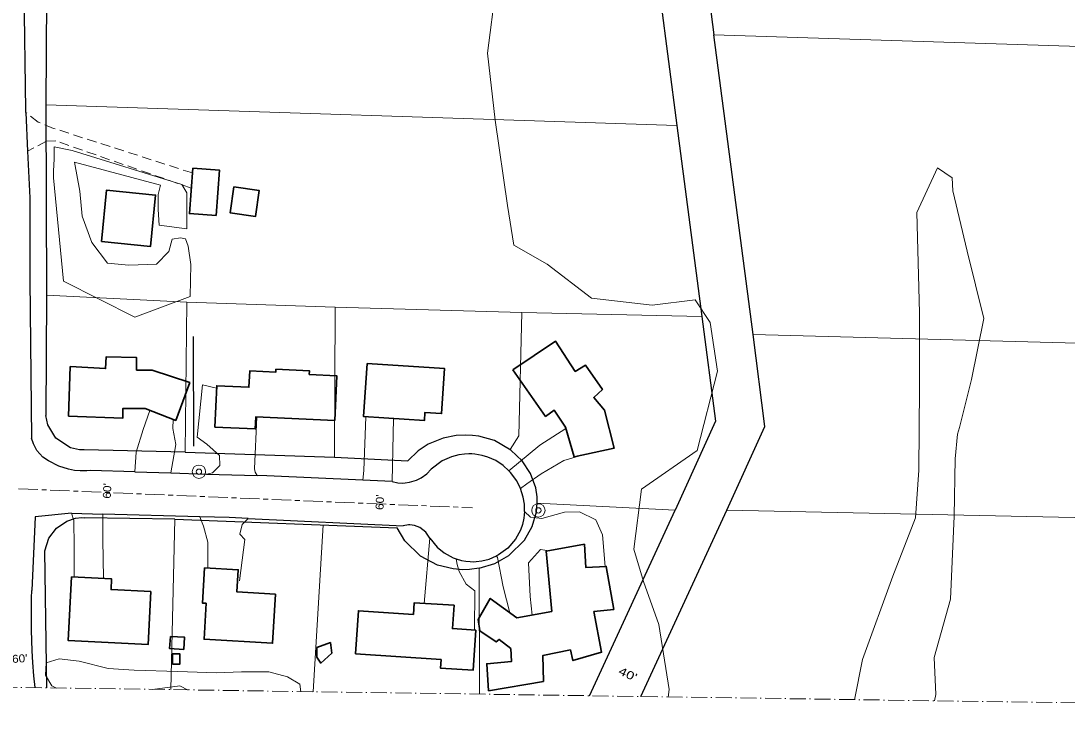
# Model space of a CAD drawing. Extents: x -861682 to -858969, y -1797841 to -1795153.
# Drawn here: x -860350 to -859566, y -1797836 to -1797317 of the extents above; entities that cross this region are included whole.
import ezdxf

# ---------------------------------------------------------------- set-up
doc = ezdxf.new("R2010")
doc.units = 0
doc.header["$LTSCALE"] = 2.4
for name, pattern in [('DOT_DASHED', [7.7, 5, -1.2, 0.3, -1.2]), ('LONG_DASH_SHORT_DASH', [9.9, 6, -1.2, 1.5, -1.2]), ('MEDIUM_DASHED', [4.5, 3, -1.5])]:
    doc.linetypes.add(name, pattern=pattern)
for name, color, linetype, lineweight in [('10', 7, 'Continuous', 25), ('11', 7, 'Continuous', 13), ('12', 7, 'Continuous', 35), ('14', 7, 'Continuous', 25), ('18', 7, 'Continuous', 13), ('30', 7, 'Continuous', 13), ('31', 7, 'Continuous', 13), ('32', 7, 'LONG_DASH_SHORT_DASH', 13), ('42', 7, 'Continuous', 25), ('61', 7, 'Continuous', 13)]:
    doc.layers.add(name, color=color, linetype=linetype, lineweight=lineweight)
doc.layers.add('43', color=7, linetype='Continuous')

msp = doc.modelspace()

# ---------------------------------------------------------------- linework, layer by layer
at = {"layer": '10'}
for p, q in [((-860346.092, -1797386.021), (-860344.837, -1797414.894)), ((-860264.541, -1797655.175), (-860297.626, -1797654.184)), ((-860264.541, -1797655.175), (-860237.512, -1797655.986)), ((-860237.512, -1797655.986), (-860210.664, -1797656.791)), ((-860210.664, -1797656.791), (-860172.696, -1797657.929)), ((-860071.585, -1797662.487), (-860093.426, -1797661.477)), ((-860311.905, -1797686.124), (-860288.485, -1797686.779)), ((-860215.707, -1797688.816), (-860288.485, -1797686.779)), ((-860179.59, -1797690.091), (-860063.186, -1797695.517))]:
    msp.add_line(p, q, dxfattribs=at)
for points in [[(-860346.092, -1797386.021), (-860346.181, -1797383.977), (-860347.486, -1797294.242), (-860348.717, -1797244.699)], [(-860344.837, -1797414.894), (-860343.319, -1797449.854), (-860343.308, -1797511.255), (-860341.886, -1797630.037)], [(-860329.301, -1797646.991), (-860333.385, -1797644.118), (-860337.927, -1797639.066), (-860340.551, -1797634.233), (-860341.886, -1797630.037)], [(-859984.071, -1797654.346), (-859988.342, -1797650.355), (-859993.871, -1797646.742), (-859999.904, -1797644.054), (-860004.131, -1797642.81), (-860009.561, -1797641.897), (-860011.759, -1797641.736), (-860013.962, -1797641.691), (-860017.264, -1797641.844), (-860021.627, -1797642.455), (-860026.949, -1797643.865), (-860033.987, -1797646.996), (-860042.218, -1797653.065), (-860045.629, -1797656.716)], [(-860297.626, -1797654.184), (-860300.412, -1797654.417), (-860302.615, -1797654.488), (-860304.263, -1797654.478), (-860305.365, -1797654.44), (-860309.753, -1797654.044), (-860314.089, -1797653.259), (-860321.447, -1797650.969), (-860329.301, -1797646.991)], [(-860093.426, -1797661.477), (-860165.596, -1797658.142), (-860172.696, -1797657.929)], [(-860071.585, -1797662.487), (-860067.268, -1797663.356), (-860063.97, -1797663.556), (-860061.768, -1797663.471), (-860058.495, -1797663.02), (-860053.231, -1797661.422), (-860049.677, -1797659.64), (-860045.629, -1797656.716)], [(-859975.225, -1797667.743), (-859978.158, -1797661.825), (-859982.714, -1797655.615), (-859984.071, -1797654.346)], [(-859972.305, -1797684.998), (-859972.265, -1797682.794), (-859972.423, -1797679.493), (-859973.269, -1797674.052), (-859975.225, -1797667.743)], [(-860311.905, -1797686.124), (-860339.289, -1797688.832), (-860341.665, -1797744.103)], [(-860179.59, -1797690.091), (-860193.81, -1797689.429), (-860215.707, -1797688.816)], [(-859972.305, -1797684.998), (-859972.778, -1797689.972), (-859973.828, -1797694.635), (-859975.298, -1797698.788), (-859978.972, -1797705.557), (-859984.713, -1797712.221), (-859991.814, -1797717.414), (-859993.235, -1797718.044)], [(-860043.312, -1797704.884), (-860046.369, -1797700.328), (-860050.716, -1797696.982), (-860054.822, -1797695.413), (-860058.237, -1797694.951), (-860059.339, -1797694.951), (-860063.186, -1797695.517)], [(-860043.312, -1797704.884), (-860037.71, -1797711.667), (-860032.579, -1797715.824), (-860025.804, -1797719.485), (-860023.446, -1797720.239)], [(-860023.446, -1797720.239), (-860019.514, -1797721.499), (-860016.264, -1797722.096), (-860012.974, -1797722.413), (-860010.771, -1797722.468), (-860008.568, -1797722.397), (-860004.193, -1797721.878), (-859998.854, -1797720.536), (-859993.235, -1797718.044)], [(-860339.286, -1797816.837), (-860340.159, -1797807.958), (-860340.924, -1797798.07), (-860341.44, -1797789.269), (-860341.765, -1797781.562), (-860341.973, -1797773.851), (-860342.038, -1797769.443), (-860342.065, -1797765.035), (-860342.065, -1797763.933), (-860342.053, -1797760.627), (-860342.002, -1797756.22), (-860341.854, -1797749.609), (-860341.665, -1797744.103)]]:
    msp.add_lwpolyline(points, dxfattribs=at)
at = {"layer": '11'}
for p, q in [((-860070.432, -1797615.281), (-860071.585, -1797662.487)), ((-860206.225, -1797655.944), (-860210.664, -1797656.791)), ((-860047.565, -1797753.678), (-860043.312, -1797704.884))]:
    msp.add_line(p, q, dxfattribs=at)
at = {"layer": '11', "linetype": 'MEDIUM_DASHED'}
for points in [[(-860221.335, -1797431.244), (-860325.343, -1797397.827), (-860336.934, -1797393.151), (-860346.092, -1797386.021)], [(-860222.156, -1797442.594), (-860323.652, -1797407.267), (-860330.736, -1797407.532), (-860344.837, -1797414.894)]]:
    msp.add_lwpolyline(points, dxfattribs=at)
at = {"layer": '11'}
for points in [[(-860203.161, -1797592.533), (-860213.809, -1797590.084), (-860217.667, -1797629.303), (-860210.561, -1797634.47), (-860201.081, -1797642.934), (-860200.815, -1797650.49), (-860206.225, -1797655.944)], [(-860253.14, -1797609.117), (-860258.31, -1797623.562), (-860263.439, -1797640.35), (-860264.541, -1797655.175)], [(-860235.636, -1797615.894), (-860235.878, -1797622.764), (-860233.705, -1797634.563), (-860237.512, -1797655.986)], [(-860173.087, -1797614.042), (-860174.827, -1797652.984), (-860174.345, -1797655.343), (-860172.696, -1797657.929)], [(-860091.193, -1797613.929), (-860092.874, -1797654.072), (-860093.426, -1797661.477)], [(-859941.369, -1797622.686), (-859960.934, -1797635.123), (-859984.071, -1797654.346)], [(-859930.166, -1797642.91), (-859942.704, -1797646.622), (-859959.904, -1797656.609), (-859970.501, -1797664.209), (-859975.225, -1797667.743)], [(-860310.055, -1797734.176), (-860309.915, -1797711.149), (-860310.23, -1797691.549), (-860311.905, -1797686.124)], [(-860287.923, -1797735.037), (-860288.446, -1797705.868), (-860288.485, -1797686.779)], [(-860209.717, -1797727.203), (-860209.795, -1797707.913), (-860212.913, -1797695.882), (-860215.707, -1797688.816)], [(-859911.916, -1797726.126), (-859913.904, -1797702.477), (-859918.909, -1797691.161), (-859930.978, -1797685.069), (-859942.312, -1797685.351), (-859959.297, -1797690.142), (-859967.802, -1797689.231), (-859972.305, -1797684.998)], [(-860185.951, -1797736.843), (-860181.936, -1797705.913), (-860185.73, -1797701.913), (-860184.106, -1797694.585), (-860179.59, -1797690.091)], [(-860009.829, -1797773.717), (-860009.618, -1797744.425), (-860016.015, -1797739.255), (-860021.249, -1797729.829), (-860022.923, -1797724.641), (-860023.446, -1797720.239)], [(-859983.274, -1797760.839), (-859988.376, -1797741.27), (-859992.479, -1797719.323), (-859993.235, -1797718.044)], [(-859953.755, -1797714.25), (-859960.385, -1797713.29), (-859969.319, -1797723.245), (-859968.037, -1797748.509), (-859966.661, -1797762.493)]]:
    msp.add_lwpolyline(points, dxfattribs=at)
at = {"layer": '12'}
for points in [[(-860221.074, -1797427.635), (-860223.536, -1797461.653), (-860203.572, -1797463.098), (-860201.109, -1797429.08)], [(-860289.577, -1797482.7), (-860252.721, -1797486.331), (-860248.926, -1797447.814), (-860285.782, -1797444.183)], [(-860190.317, -1797441.682), (-860193.073, -1797461.058), (-860173.967, -1797463.776), (-860171.21, -1797444.401)], [(-859980.997, -1797578.759), (-859956.533, -1797613.613), (-859950.175, -1797608.864), (-859941.622, -1797621.819), (-859935.156, -1797643.992), (-859905.19, -1797637.496), (-859912.389, -1797608.949), (-859920.456, -1797599.535), (-859913.868, -1797593.368), (-859926.694, -1797575.235), (-859934.232, -1797579.988), (-859948.965, -1797557.376)], [(-860313.053, -1797576.312), (-860314.085, -1797613.394), (-860273.459, -1797614.884), (-860273.487, -1797607.799), (-860256.72, -1797607.732), (-860233.777, -1797616.614), (-860223.263, -1797588.233), (-860251.404, -1797578.899), (-860263.212, -1797578.946), (-860263.25, -1797569.5), (-860285.924, -1797568.882), (-860286.36, -1797577.858)], [(-860114.514, -1797616.607), (-860173.801, -1797614.011), (-860174.193, -1797622.966), (-860204.436, -1797621.642), (-860203.082, -1797590.708), (-860178.892, -1797591.767), (-860178.357, -1797579.553), (-860158.753, -1797580.412), (-860158.659, -1797578.276), (-860133.534, -1797579.382), (-860133.659, -1797582.21), (-860113.033, -1797583.122)], [(-860090.36, -1797574.001), (-860032.248, -1797577.783), (-860034.443, -1797611.517), (-860046.932, -1797610.704), (-860047.328, -1797616.786), (-860092.952, -1797613.815)], [(-859999.399, -1797819.246), (-859958.098, -1797812.232), (-859958.648, -1797792.868), (-859937.883, -1797788.534), (-859935.962, -1797796.556), (-859914.496, -1797790.33), (-859920.286, -1797759.888), (-859905.414, -1797758.175), (-859910.975, -1797726.079), (-859926.322, -1797726.849), (-859927.337, -1797709.377), (-859956.127, -1797714.688), (-859951.932, -1797759.779), (-859978.127, -1797764.607), (-859998.023, -1797750.045), (-860007.17, -1797765.668), (-860005.718, -1797774.4), (-859993.641, -1797782.617), (-859991.287, -1797780.719), (-859982.522, -1797787.532), (-859982.011, -1797797.213), (-860000.661, -1797798.941)], [(-860212.315, -1797727.051), (-860213.862, -1797753.507), (-860211.038, -1797753.672), (-860212.61, -1797780.57), (-860161.184, -1797783.576), (-860159.037, -1797746.841), (-860187.889, -1797745.155), (-860186.918, -1797728.534)], [(-860311.948, -1797733.826), (-860314.355, -1797781.541), (-860254.535, -1797784.559), (-860252.531, -1797744.835), (-860282.31, -1797743.333), (-860281.907, -1797735.34)], [(-860098.934, -1797791.541), (-860034.917, -1797795.772), (-860035.339, -1797802.152), (-860010.883, -1797803.77), (-860008.899, -1797773.779), (-860026.307, -1797772.627), (-860025.151, -1797755.162), (-860054.964, -1797753.189), (-860055.543, -1797761.934), (-860096.793, -1797759.203)], [(-860237.851, -1797778.401), (-860227.221, -1797779.067), (-860227.796, -1797788.239), (-860238.426, -1797787.572)], [(-860128.002, -1797786.698), (-860127.972, -1797794.019), (-860125.12, -1797798.495), (-860116.649, -1797790.904), (-860117.861, -1797783.115)], [(-860236.145, -1797791.619), (-860230.713, -1797791.598), (-860230.684, -1797799.155), (-860236.115, -1797799.176)]]:
    msp.add_lwpolyline(points, close=True, dxfattribs=at)
at = {"layer": '14'}
msp.add_line((-860220.238, -1797635.926), (-860220.568, -1797553.743), dxfattribs=at)
at = {"layer": '18'}
for points in [[(-859864.604, -1797823.876), (-859863.846, -1797818.232), (-859871.598, -1797769.614), (-859883.064, -1797737.305), (-859890.246, -1797713.009), (-859884.522, -1797668.116), (-859842.837, -1797639.137), (-859827.724, -1797579.799), (-859833.066, -1797543.215), (-859844.47, -1797526.257), (-859876.572, -1797530.401), (-859922.172, -1797525.152), (-859955.337, -1797499.543), (-859980.428, -1797485.237), (-859985.033, -1797455.735), (-859994.264, -1797391.772), (-860000.133, -1797341.493), (-859993.716, -1797292.818)], [(-859664.994, -1797826.768), (-859663.802, -1797821.918), (-859665.093, -1797794.293), (-859652.988, -1797750.554), (-859650.167, -1797688.432), (-859649.394, -1797645.447), (-859647.579, -1797627.019), (-859646.185, -1797621.821), (-859637.119, -1797585.888), (-859627.855, -1797540.272), (-859640.338, -1797489.783), (-859651.146, -1797444.719), (-859651.658, -1797434.802), (-859662.787, -1797427.29), (-859678.24, -1797460.887), (-859676.049, -1797535.978), (-859676.06, -1797592.185), (-859676.758, -1797653.826), (-859679.213, -1797689.496), (-859696.277, -1797733.255), (-859718.935, -1797795.693), (-859724.851, -1797825.901)], [(-860323.199, -1797817.233), (-860326.736, -1797815.599), (-860331.491, -1797807.589), (-860331.057, -1797798.141), (-860321.149, -1797795.267), (-860306.264, -1797797.097), (-860284.515, -1797802.441), (-860264.909, -1797803.78), (-860232.314, -1797804.83), (-860203.262, -1797805.658), (-860184.608, -1797805.111), (-860164.062, -1797805.029), (-860150.113, -1797808.751), (-860140.645, -1797814.145), (-860139.938, -1797819.887)], [(-860251.296, -1797818.274), (-860251.297, -1797818.274), (-860251.298, -1797818.274), (-860251.299, -1797818.274)], [(-860224.456, -1797818.663), (-860230.854, -1797815.451), (-860251.296, -1797818.274)]]:
    msp.add_lwpolyline(points, dxfattribs=at)
msp.add_lwpolyline([(-860224.382, -1797485.98), (-860222.437, -1797499.906), (-860223.05, -1797523.761), (-860264.553, -1797539.278), (-860318.033, -1797512.333), (-860325.429, -1797434.902), (-860325.45, -1797429.707), (-860325.013, -1797420.967), (-860325.05, -1797411.757), (-860311.577, -1797414.537), (-860229.291, -1797439.949), (-860225.488, -1797446.074), (-860225.422, -1797462.369), (-860225.38, -1797472.996), (-860246.173, -1797470.246), (-860246.928, -1797458.677), (-860246.973, -1797447.341), (-860245.348, -1797440.486), (-860309.653, -1797423.268), (-860305.787, -1797444.979), (-860304.06, -1797463.629), (-860296.659, -1797483.437), (-860285.026, -1797498.741), (-860268.96, -1797500.33), (-860248.181, -1797499.538), (-860239.009, -1797490.055), (-860236.448, -1797480.834), (-860230.312, -1797479.865), (-860226.53, -1797480.558)], close=True, dxfattribs=at)
at = {"layer": '30'}
for p, q in [((-860331.158, -1797380.209), (-859858.095, -1797395.812)), ((-860330.766, -1797522.891), (-860225.419, -1797528.102)), ((-860225.419, -1797528.102), (-860226.653, -1797640.302)), ((-860225.419, -1797528.102), (-860114.204, -1797531.794)), ((-860114.803, -1797644.194), (-860114.204, -1797531.794)), ((-860114.204, -1797531.794), (-859974.267, -1797535.751)), ((-859839.326, -1797538.824), (-859974.267, -1797535.751)), ((-859800.987, -1797552.375), (-859419.905, -1797562.367)), ((-859962.823, -1797678.712), (-859859.299, -1797683.811)), ((-859032.746, -1797700.43), (-859820.703, -1797683.867)), ((-860237.466, -1797818.324), (-860234.379, -1797690.727)), ((-860130.761, -1797819.883), (-860123.3, -1797694.919)), ((-860006.053, -1797821.706), (-860006.266, -1797727.381))]:
    msp.add_line(p, q, dxfattribs=at)
for points in [[(-859830.296, -1797327.703), (-859414.772, -1797341.094), (-859296.184, -1797345.606)], [(-859983.169, -1797638.453), (-859976.498, -1797628.284), (-859974.267, -1797535.751)]]:
    msp.add_lwpolyline(points, dxfattribs=at)
at = {"layer": '31'}
for centre, radius in [((-860216.383, -1797655.039), 5), ((-860216.383, -1797655.039), 2), ((-859961.919, -1797684.013), 5), ((-859961.919, -1797684.013), 2)]:
    msp.add_circle(centre, radius, dxfattribs=at)
at = {"layer": '32'}
msp.add_line((-860351.582, -1797667.88), (-860011.297, -1797682.093), dxfattribs=at)
at = {"layer": '42'}
for p, q in [((-860330.383, -1797229.358), (-860331.158, -1797380.209)), ((-859877.808, -1797244.282), (-859858.095, -1797395.812)), ((-860331.158, -1797380.209), (-860330.766, -1797522.891)), ((-859858.095, -1797395.812), (-859839.326, -1797538.824)), ((-860330.766, -1797522.891), (-860331.097, -1797612.953)), ((-860226.653, -1797640.302), (-860302.407, -1797638.773)), ((-860226.653, -1797640.302), (-860114.803, -1797644.194)), ((-860114.803, -1797644.194), (-860059.896, -1797646.866)), ((-859923.535, -1797822.911), (-859859.299, -1797683.811)), ((-859885.112, -1797823.473), (-859820.703, -1797683.867)), ((-860234.379, -1797690.727), (-860301.953, -1797689.497)), ((-860234.379, -1797690.727), (-860067.888, -1797697.01)), ((-860330.499, -1797816.944), (-860331.944, -1797714.436))]:
    msp.add_line(p, q, dxfattribs=at)
for points in [[(-859737.749, -1796947.769), (-859849.278, -1797180.786), (-859830.296, -1797327.703)], [(-859820.703, -1797683.867), (-859792.054, -1797621.181), (-859800.987, -1797552.375), (-859830.296, -1797327.703)], [(-859839.326, -1797538.824), (-859829.084, -1797617.248), (-859859.299, -1797683.811)], [(-860302.407, -1797638.773), (-860305.962, -1797638.71), (-860312.688, -1797637.272), (-860323.655, -1797630), (-860329.66, -1797619.903), (-860331.097, -1797612.953)], [(-860006.266, -1797727.381), (-859994.642, -1797723.766), (-859984.163, -1797717.837), (-859972.4, -1797706.247), (-859966.644, -1797696.193), (-859963.433, -1797685.229), (-859962.798, -1797678.445), (-859962.922, -1797673.912), (-859963.93, -1797667.189), (-859967.739, -1797656.486), (-859974.035, -1797646.873), (-859982.501, -1797638.831), (-859994.928, -1797631.807), (-860006.565, -1797628.48), (-860011.406, -1797627.838), (-860016.296, -1797627.599), (-860023.635, -1797627.998), (-860033.22, -1797629.932), (-860044.444, -1797634.507), (-860052.12, -1797639.485), (-860059.896, -1797646.866)], [(-860331.944, -1797714.436), (-860328.888, -1797704.757), (-860323.157, -1797697.42), (-860315.454, -1797692.181), (-860308.847, -1797689.991), (-860304.258, -1797689.467), (-860301.953, -1797689.497)], [(-860006.266, -1797727.381), (-860013.548, -1797728.356), (-860018.449, -1797728.497), (-860025.771, -1797727.938), (-860037.567, -1797724.996), (-860050.32, -1797718.356), (-860062.114, -1797706.963), (-860067.888, -1797697.01)]]:
    msp.add_lwpolyline(points, dxfattribs=at)
at = {"layer": '61', "linetype": 'DOT_DASHED'}
msp.add_lwpolyline([(-861676.699, -1797797.295), (-859488.961, -1797829.261), (-859035.9, -1797835.881)], dxfattribs=at)

# ---------------------------------------------------------------- texts
at = {"layer": '43'}
for s, rotation, width, p in [("60'", 87.274, 1.1, (-860282.543, -1797675.345)), ("60'", 87.663, 1.1, (-860078.069, -1797683.811)), ("60'", 3.518, 1.1, (-860356.322, -1797798.372)), ("40'", 335.215, 1.35, (-859902.471, -1797806.452))]:
    msp.add_text(s, height=6, rotation=rotation, dxfattribs=dict(at, width=width)).set_placement(p)

doc.saveas('drawing.dxf')
